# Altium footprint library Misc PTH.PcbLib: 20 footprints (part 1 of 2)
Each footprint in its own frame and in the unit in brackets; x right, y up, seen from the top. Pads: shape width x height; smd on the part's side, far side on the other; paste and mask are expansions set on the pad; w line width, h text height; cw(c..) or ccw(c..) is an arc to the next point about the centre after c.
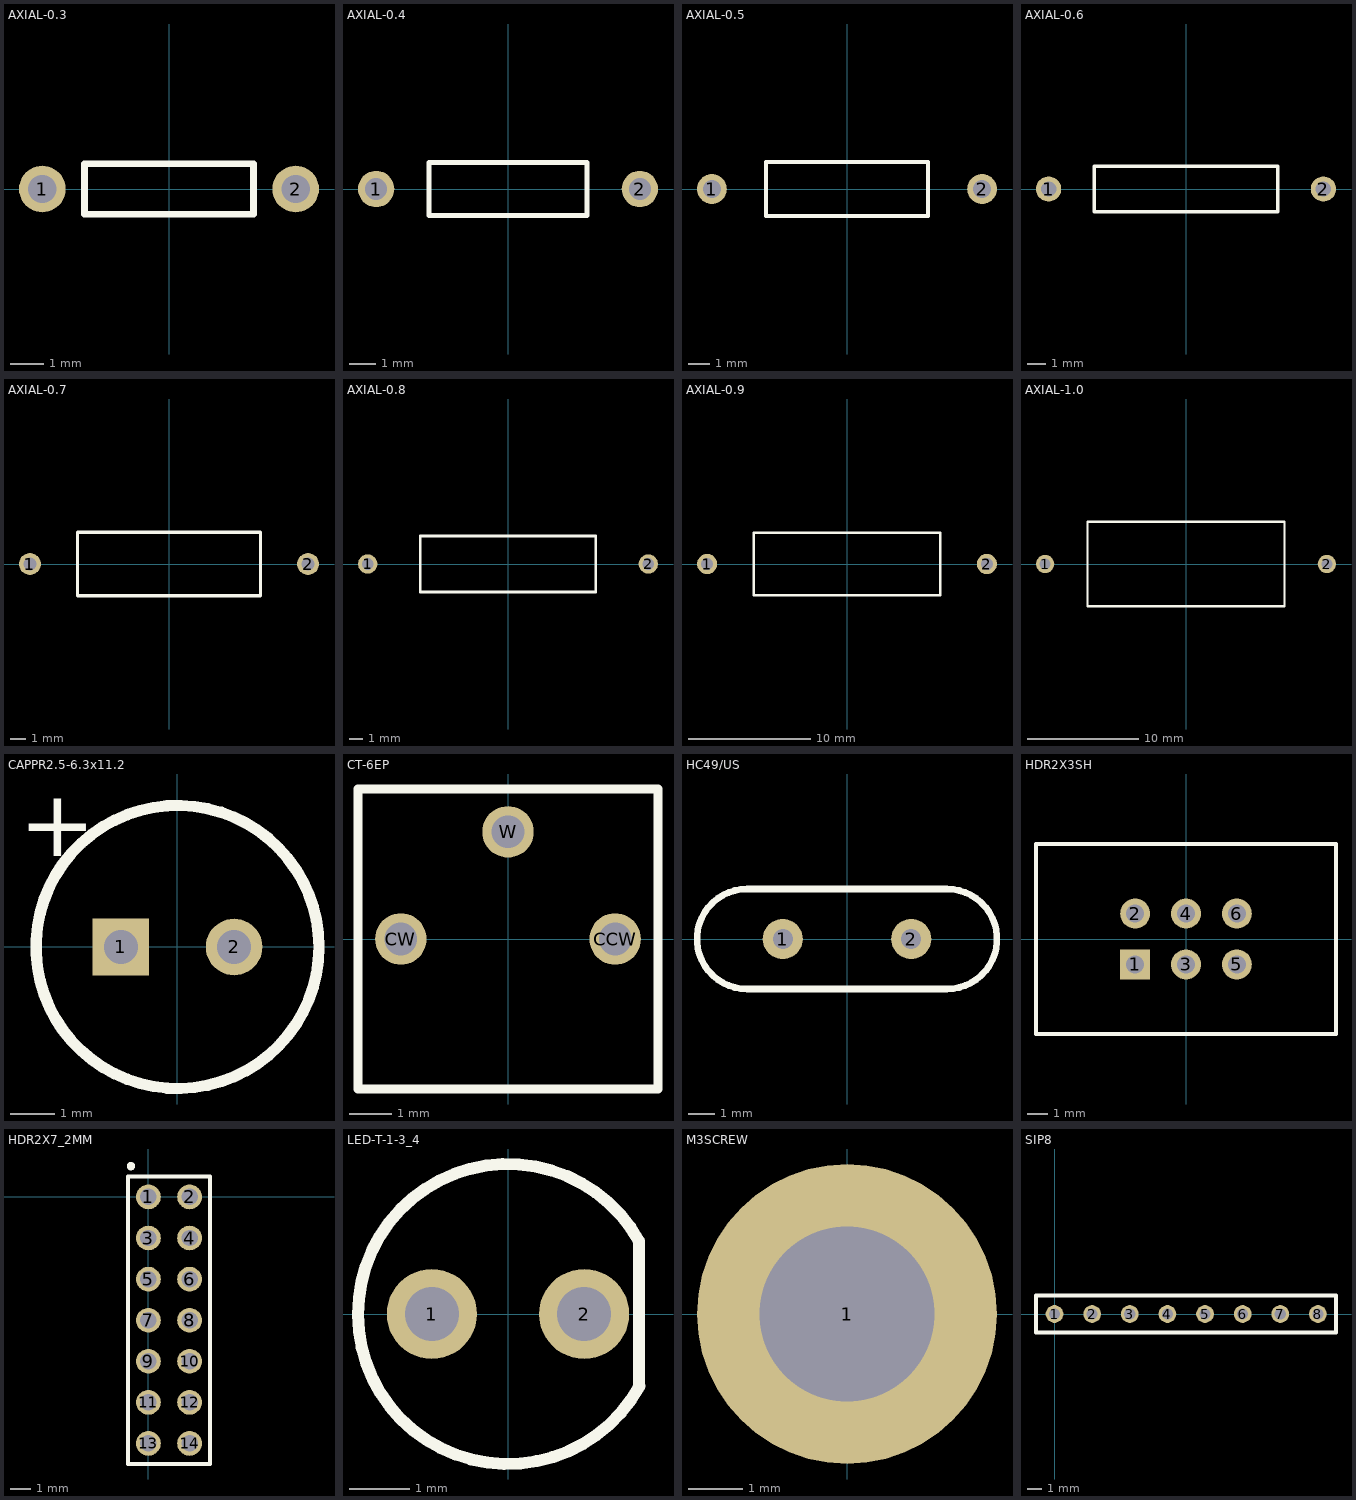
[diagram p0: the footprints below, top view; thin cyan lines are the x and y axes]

## AXIAL-0.3 [mm] "Axial Device, Thru-Hole; 2 Leads; 0.3 in Pin Spacing"
height 1.524
pads (2):
  round 1.4 hole 0.85: 1(-3.81,0) 2(3.81,0)
Top Overlay:
  lines w0.2: -2.54,-0.762 -2.54,0.762 2.54,0.762 2.54,0 2.54,-0.762 -2.54,-0.762

## AXIAL-0.4 [mm] "Axial Device, Thru-Hole; 2 Leads; 0.4 in Pin Spacing"
height 2.032
pads (2):
  round 1.4 hole 0.85: 1(-5.08,0) 2(5.08,0)
Top Overlay:
  lines w0.2: -3.048,-1.016 -3.048,1.016 3.048,1.016 3.048,-1.016 -3.048,-1.016

## AXIAL-0.5 [mm] "Axial Device, Thru-Hole; 2 Leads; 0.5 in Pin Spacing"
height 2.54
pads (2):
  round 1.4 hole 0.85: 1(-6.35,0) 2(6.35,0)
Top Overlay:
  lines w0.2: -3.81,-1.27 3.81,-1.27 3.81,1.27 -3.81,1.27 -3.81,-1.27

## AXIAL-0.6 [mm] "Axial Device, Thru-Hole; 2 Leads; 0.6 in Pin Spacing"
height 2.54
pads (2):
  round 1.4 hole 0.85: 1(-7.62,0) 2(7.62,0)
Top Overlay:
  lines w0.2: -5.08,-1.27 -5.08,1.27 5.08,1.27 5.08,-1.27 -5.08,-1.27

## AXIAL-0.7 [mm] "Axial Device, Thru-Hole; 2 Leads; 0.7 in Pin Spacing"
height 4.064
pads (2):
  round 1.4 hole 0.85: 1(-8.89,0) 2(8.89,0)
Top Overlay:
  lines w0.2: -5.842,-2.032 5.842,-2.032 5.842,2.032 -5.842,2.032 -5.842,-2.032

## AXIAL-0.8 [mm] "Axial Device, Thru-Hole; 2 Leads; 0.8 in Pin Spacing"
height 4.064
pads (2):
  round 1.4 hole 0.85: 1(-10.16,0) 2(10.16,0)
Top Overlay:
  lines w0.2: -6.35,-2.032 6.35,-2.032 6.35,2.032 -6.35,2.032 -6.35,-2.032

## AXIAL-0.9 [mm] "Axial Device, Thru-Hole; 2 Leads; 0.9 in Pin Spacing"
height 5.08
pads (2):
  round 1.65 hole 1: 1(-11.43,0) 2(11.43,0)
Top Overlay:
  lines w0.2: -7.62,-2.54 -7.62,2.54 7.62,2.54 7.62,-2.54 -7.62,-2.54

## AXIAL-1.0 [mm] "Axial Device, Thru-Hole; 2 Leads; 1.0 in Pin Spacing"
height 7.62
pads (2):
  round 1.65 hole 1: 1(-12.7,0) 2(12.7,0)
Top Overlay:
  lines w0.2: -8.89,-3.81 8.89,-3.81 8.89,3.81 -8.89,3.81 -8.89,-3.81

## CAPPR2.5-6.3x11.2 [mil] "Capacitor, Electrolytic, Radial; Body 6.3 x 11.2 mm (Dia.xH typ); Pin Spacing 2.5 mm (typ)"
height 440.94
pads (2):
  rect 50x50 hole 30: 1(-50,0)
  round 50 hole 30: 2(50,0)
Top Overlay:
  circle w10: c0,0 r125
  text "+" at -140,80 h59.06

## CT-6EP [mm] "Trimmer Potentiometer (Copal)"
height 5.8
pads (3):
  round 1.2 hole 0.762: CCW(2.5,0) CW(-2.5,0) W(0,2.5)
Top Overlay:
  lines w0.2: -3.5,-3.5 -3.5,3.5 3.5,3.5 3.5,-3.5 -3.5,-3.5

## HC49/US [mil] "Low-profile crystal resonator"
height 137.8
pads (2):
  round 60 hole 30: 1(-96.06,0) 2(96.06,0)
Top Overlay:
  lines w10: -149.61,-74.8 cw(c-149.61,0) -149.61,74.8 149.61,74.8 cw(c149.61,0) 149.61,-74.8 -149.61,-74.8
3D body: height 144.88, standoff -78.74, extent -250,-96.85 250,100

## HDR2X3SH [mm] "Connector; Header; 3x2 Position"
pads (6):
  rect 1.5x1.5 hole 0.9: 1(-2.54,-1.27)
  round 1.5 hole 0.9: 2(-2.54,1.27) 3(0,-1.27) 4(0,1.27) 5(2.54,-1.27) 6(2.54,1.27)
Top Overlay:
  lines w0.2: -7.5,-4.75 -7.5,4.75 7.5,4.75 7.5,-4.75 -7.5,-4.75

## HDR2X7_2MM [mm]
pads (14):
  round 1.2 hole 0.8: 1(0,0) 2(2,0) 3(0,-2) 4(2,-2) 5(0,-4) 6(2,-4) 7(0,-6) 8(2,-6) 9(0,-8) 10(2,-8) 11(0,-10) 12(2,-10) 13(0,-12) 14(2,-12)
Top Overlay:
  circle w0.2: c-0.853,1.5 r0.103
  lines w0.2: -1,-13 -1,1 3,1 3,-13 -1,-13

## LED-T-1-3_4 [mm] "LED 5mm T-1 3/4"
height 8.6
pads (2):
  round 1.5 hole 0.9 mask+0: 1(-1.27,0) 2(1.27,0)
Top Overlay:
  lines w0.2: 2.185,-1.188 2.185,1.214 ccw(c0,0) 2.195,-1.197
3D body: height 8.6, standoff -1, extent -2.95,-2.949 2.5,2.949

## M3SCREW [mm]
pads (1):
  round 5.5 hole 3.2: 1(0,0)

## SIP8 [mm] "Single in-line package"
height 5
pads (8):
  round 1.2 hole 0.75: 1(0,0) 2(2.54,0) 3(5.08,0) 4(7.62,0) 5(10.16,0) 6(12.7,0) 7(15.24,0) 8(17.78,0)
Top Overlay:
  lines w0.254: -1.25,-1.25 19,-1.25 19,1.25 -1.25,1.25 -1.25,-1.25
3D body: height 5, standoff 0, extent -1.25,-1.25 19,1.25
